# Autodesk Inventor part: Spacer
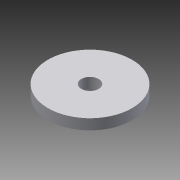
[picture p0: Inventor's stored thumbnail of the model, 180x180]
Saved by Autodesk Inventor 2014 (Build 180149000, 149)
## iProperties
Shininess: 9.0
Length Units: 11272
Angle Units: 11279
Time Units: 11290
Mass Units: 11286
Length Display Precision: 3
Angle Display Precision: 2
Compacted: True
Created: 2001-11
Part Number: Spacer
Document SubType Name: Modeling
Designer: Autodesk, Inc.
Mass: 0.788664 g
Surface Area: 8.16584 cm^2
Volume: 0.788664 cm^3
Density: 1 g/cm^3
Material: Generic
Appearance: White (Flat)
Density: 0.0
Volumn: 0.0
Area: 0.0
PropertySet Name: Model Information
Control State: 0
Master: False
Checked Out: False
Author: Autodesk, Inc.
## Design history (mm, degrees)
sketch "Sketch1"
  geometry: L1 (162.642, 127.182)-(154.578, 127.182); L2 (162.642, 129.722)-(162.642, 127.182); L3 (154.578, 129.722)-(162.642, 129.722); L4 (154.578, 127.182)-(154.578, 129.722); L5 (152.482, 125.089)-(152.482, 131.695); L6 (152.482, 125.089)-(152.482, 131.695)
  constraints: 12 end point, 3 vertical, 2 horizontal, 1 other
  dimensions: "d1" = 8.0645 distance of L3.start L2.start; "d2" = 2.0955 distance between parallel lines of L5 L4; "d3" = 2.54 distance of L2.start L1.start
revolve "RevolutionFull1" sketch "Sketch1" stored, may be unused: angle "d0" = 360 deg
body "Solid1"
